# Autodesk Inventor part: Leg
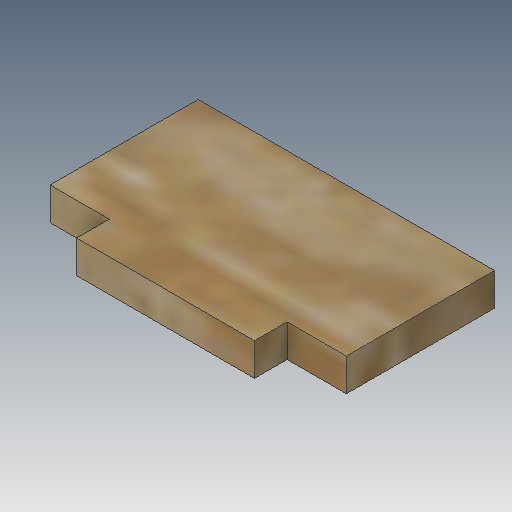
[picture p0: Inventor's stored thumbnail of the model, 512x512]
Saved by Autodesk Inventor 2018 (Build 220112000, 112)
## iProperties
Created: 2018-05
Part Number: Leg
Material: Generic
Document SubType Name: Modeling
Designer: arivu
Density: 1 g/cm^3
Appearance: Default
Author: arivu
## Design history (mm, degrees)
derived "WaterTank.ipt"
feature "Solid3::WaterTank.ipt" dims "d0" = 10
tag "TaggingFeature1"
body "Solid1"
